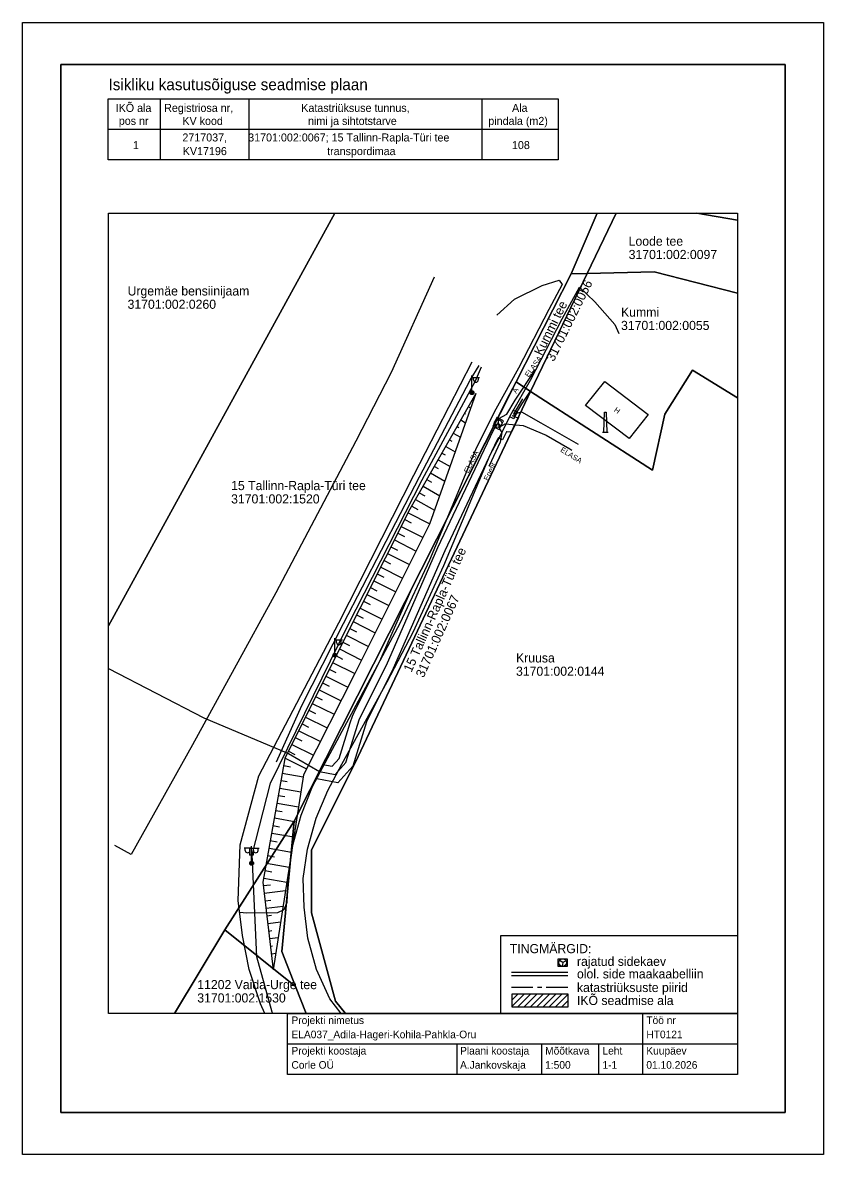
# Model space of a CAD drawing. Extents: x 544680 to 544785, y 6560513 to 6560661.
import ezdxf

# ---------------------------------------------------------------- set-up
doc = ezdxf.new("R2010")
doc.units = 0
for name, color, linetype in [('AED', 7, 'Continuous'), ('HOONE', 7, 'Continuous'), ('KASUTUSALA', 7, 'Continuous'), ('LIIKLUS', 7, 'Continuous'), ('PIIR', 7, 'Continuous'), ('POST', 7, 'Continuous'), ('PR_SIDE', 7, 'Continuous'), ('RAJATIS', 7, 'Continuous'), ('RELJEEF', 7, 'Continuous'), ('SITRASS', 7, 'Continuous'), ('TEE', 7, 'Continuous'), ('VORMISTUS', 7, 'Continuous')]:
    doc.layers.add(name, color=color, linetype=linetype)

msp = doc.modelspace()

# ---------------------------------------------------------------- linework, layer by layer
at = {"layer": 'AED'}
msp.add_lwpolyline([(544713.28, 6560564.18), (544716.58, 6560571.59), (544722.06, 6560582.33), (544722.06, 6560582.33), (544732.03, 6560601.58), (544732.03, 6560601.58), (544738.66, 6560614.26), (544739.83, 6560616.2)], dxfattribs=at)
at = {"layer": 'HOONE'}
msp.add_lwpolyline([(544762.01, 6560609.75), (544759.49, 6560606.62), (544753.8, 6560610.95), (544756.32, 6560614.08), (544762.01, 6560609.75)], dxfattribs=at)
at = {"layer": 'KASUTUSALA'}
msp.add_lwpolyline([(544720.57, 6560563.6), (544721.48, 6560564.61), (544722.94, 6560569.31), (544723.22, 6560570.2), (544723.64, 6560571.04), (544726.77, 6560577.29), (544731.03, 6560587.02), (544743.83, 6560612.38), (544744.68, 6560614.07), (544746.52, 6560612.82), (544745.39, 6560611.12), (544744.4, 6560609.44), (544744.98, 6560609.39), (544744.07, 6560607.46), (544743.45, 6560607.51), (544743.42, 6560607.5), (544742.91, 6560606.44), (544742.35, 6560606.71), (544742.21, 6560606.43), (544735.34, 6560591.89), (544728.58, 6560576.44), (544725.08, 6560569.45), (544723.26, 6560563.6), (544721.3, 6560561.42), (544718.56, 6560561.96), (544718.42, 6560562.04), (544719.33, 6560563.85)], close=True, dxfattribs=at)
at = {"layer": 'LIIKLUS'}
for p, q in [((544709.71, 6560552.8), (544709.71, 6560551.95)), ((544710.21, 6560552.8), (544709.71, 6560552.8)), ((544710.21, 6560551.95), (544709.71, 6560551.95)), ((544709.96, 6560551.95), (544709.96, 6560551.05)), ((544710.21, 6560552.8), (544710.21, 6560551.95)), ((544710.21, 6560551.05), (544709.96, 6560551.05))]:
    msp.add_line(p, q, dxfattribs=at)
at = {"layer": 'PIIR'}
for p, q in [((544691.22, 6560582.03), (544720.91, 6560636.18)), ((544720.91, 6560636.18), (544691.22, 6560582.03)), ((544768.39, 6560636.18), (544773.72, 6560635.28)), ((544773.72, 6560635.28), (544768.39, 6560636.18))]:
    msp.add_line(p, q, dxfattribs=at)
for points in [[(544699.87, 6560531.18), (544706.47, 6560542.13), (544715.57, 6560556.4), (544744.68, 6560614.07), (544751.91, 6560628.23), (544755.32, 6560636.18)], [(544755.32, 6560636.18), (544751.91, 6560628.23), (544754.02, 6560628.26), (544757.82, 6560636.18)], [(544757.82, 6560636.18), (544754.02, 6560628.26), (544762.78, 6560628.47), (544773.72, 6560625.67)], [(544773.72, 6560625.67), (544762.78, 6560628.47), (544754.02, 6560628.26), (544746.58, 6560612.78), (544762.55, 6560602.44), (544764.17, 6560609.79), (544767.79, 6560615.57), (544773.72, 6560611.93)], [(544773.72, 6560611.93), (544767.79, 6560615.57), (544764.17, 6560609.79), (544762.55, 6560602.44), (544746.58, 6560612.78), (544723.97, 6560564.88), (544717.87, 6560552.58), (544717.86, 6560544.37), (544720.99, 6560532.77), (544722.29, 6560531.18)], [(544722.29, 6560531.18), (544720.99, 6560532.77), (544717.86, 6560544.37), (544717.87, 6560552.58), (544723.97, 6560564.88), (544746.58, 6560612.78), (544744.68, 6560614.07), (544715.57, 6560556.4), (544713.97, 6560539.29), (544715.73, 6560534.7), (544717.15, 6560531.18)], [(544717.15, 6560531.18), (544715.73, 6560534.7), (544706.47, 6560542.13), (544699.87, 6560531.18)]]:
    msp.add_lwpolyline(points, dxfattribs=at)
for points in [[(544751.91, 6560628.23), (544744.68, 6560614.07), (544746.58, 6560612.78), (544754.02, 6560628.26)], [(544715.73, 6560534.7), (544713.97, 6560539.29), (544715.57, 6560556.4), (544706.47, 6560542.13)]]:
    msp.add_lwpolyline(points, close=True, dxfattribs=at)
at = {"layer": 'POST'}
for p, q in [((544738.89, 6560612.88), (544738.89, 6560614.88)), ((544738.89, 6560612.88), (544738.89, 6560614.88)), ((544738.89, 6560614.63), (544739.89, 6560614.63)), ((544738.89, 6560614.63), (544739.89, 6560614.63)), ((544739.11, 6560614.31), (544739.11, 6560614.63)), ((544739.11, 6560614.31), (544739.11, 6560614.63)), ((544739.73, 6560614.31), (544739.73, 6560614.63)), ((544739.73, 6560614.31), (544739.73, 6560614.63)), ((544738.89, 6560612.63), (544738.89, 6560612.63)), ((544738.89, 6560612.63), (544738.89, 6560612.63)), ((544720.91, 6560578.43), (544720.91, 6560580.43)), ((544720.91, 6560580.18), (544721.91, 6560580.18)), ((544721.14, 6560579.86), (544721.14, 6560580.18)), ((544721.75, 6560579.86), (544721.75, 6560580.18)), ((544720.91, 6560578.18), (544720.91, 6560578.18)), ((544710, 6560552.88), (544709, 6560552.88)), ((544709.16, 6560552.56), (544709.16, 6560552.88)), ((544709.77, 6560552.56), (544709.77, 6560552.88)), ((544710, 6560551.13), (544710, 6560553.13)), ((544710, 6560552.88), (544711, 6560552.88)), ((544710.23, 6560552.56), (544710.23, 6560552.88)), ((544710.84, 6560552.56), (544710.84, 6560552.88)), ((544710, 6560550.88), (544710, 6560550.88))]:
    msp.add_line(p, q, dxfattribs=at)
msp.add_lwpolyline([(544743.86, 6560609.45), (544744.29, 6560610.35), (544744.83, 6560610.1), (544744.4, 6560609.19)], close=True, dxfattribs=at)
for centre, radius in [((544738.89, 6560612.63), 0.25), ((544738.89, 6560612.63), 0.25), ((544738.89, 6560612.63), 0.225), ((544738.89, 6560612.63), 0.225), ((544738.89, 6560612.63), 0.2), ((544738.89, 6560612.63), 0.2), ((544738.89, 6560612.63), 0.175), ((544738.89, 6560612.63), 0.175), ((544738.89, 6560612.63), 0.15), ((544738.89, 6560612.63), 0.15), ((544738.89, 6560612.63), 0.125), ((544738.89, 6560612.63), 0.125), ((544738.89, 6560612.63), 0.1), ((544738.89, 6560612.63), 0.1), ((544738.89, 6560612.63), 0.075), ((544738.89, 6560612.63), 0.075), ((544738.89, 6560612.63), 0.05), ((544738.89, 6560612.63), 0.05), ((544738.89, 6560612.63), 0.025), ((544738.89, 6560612.63), 0.025), ((544744.43, 6560609.95), 0.0304), ((544744.43, 6560609.95), 0.029), ((544744.43, 6560609.95), 0.0277), ((544744.43, 6560609.95), 0.0263), ((544744.43, 6560609.95), 0.0249), ((544744.43, 6560609.95), 0.0236), ((544744.43, 6560609.95), 0.0222), ((544744.43, 6560609.95), 0.0209), ((544744.43, 6560609.95), 0.0195), ((544744.43, 6560609.95), 0.0181), ((544744.43, 6560609.95), 0.0168), ((544744.43, 6560609.95), 0.0154), ((544744.43, 6560609.95), 0.014), ((544744.43, 6560609.95), 0.0127), ((544744.43, 6560609.95), 0.0113), ((544744.43, 6560609.95), 0.00996), ((544744.43, 6560609.95), 0.0086), ((544744.43, 6560609.95), 0.00724), ((544744.43, 6560609.95), 0.00587), ((544744.43, 6560609.95), 0.00451), ((544744.43, 6560609.95), 0.00315), ((544744.43, 6560609.95), 0.00179), ((544744.43, 6560609.95), 0.000426), ((544744.26, 6560609.59), 0.0304), ((544744.26, 6560609.59), 0.029), ((544744.26, 6560609.59), 0.0277), ((544744.26, 6560609.59), 0.0263), ((544744.26, 6560609.59), 0.0249), ((544744.26, 6560609.59), 0.0236), ((544744.26, 6560609.59), 0.0222), ((544744.26, 6560609.59), 0.0209), ((544744.26, 6560609.59), 0.0195), ((544744.26, 6560609.59), 0.0181), ((544744.26, 6560609.59), 0.0168), ((544744.26, 6560609.59), 0.0154), ((544744.26, 6560609.59), 0.014), ((544744.26, 6560609.59), 0.0127), ((544744.26, 6560609.59), 0.0113), ((544744.26, 6560609.59), 0.00996), ((544744.26, 6560609.59), 0.0086), ((544744.26, 6560609.59), 0.00724), ((544744.26, 6560609.59), 0.00587), ((544744.26, 6560609.59), 0.00451), ((544744.26, 6560609.59), 0.00315), ((544744.26, 6560609.59), 0.00179), ((544744.26, 6560609.59), 0.000426), ((544720.91, 6560578.18), 0.25), ((544720.91, 6560578.18), 0.225), ((544720.91, 6560578.18), 0.2), ((544720.91, 6560578.18), 0.175), ((544720.91, 6560578.18), 0.15), ((544720.91, 6560578.18), 0.125), ((544720.91, 6560578.18), 0.1), ((544720.91, 6560578.18), 0.075), ((544720.91, 6560578.18), 0.05), ((544720.91, 6560578.18), 0.025), ((544710, 6560550.88), 0.25), ((544710, 6560550.88), 0.225), ((544710, 6560550.88), 0.2), ((544710, 6560550.88), 0.175), ((544710, 6560550.88), 0.15), ((544710, 6560550.88), 0.125), ((544710, 6560550.88), 0.1), ((544710, 6560550.88), 0.075), ((544710, 6560550.88), 0.05), ((544710, 6560550.88), 0.025)]:
    msp.add_circle(centre, radius, dxfattribs=at)
for centre in [(544739.42, 6560614.31), (544739.42, 6560614.31), (544721.44, 6560579.86), (544709.47, 6560552.56), (544710.53, 6560552.56)]:
    msp.add_arc(centre, 0.306, 180, 0, dxfattribs=at)
at = {"layer": 'PR_SIDE'}
for p, q in [((544742.31, 6560608.57), (544741.89, 6560608.29)), ((544742.31, 6560609.07), (544742.31, 6560608.57)), ((544742.31, 6560608.57), (544742.72, 6560608.29))]:
    msp.add_line(p, q, dxfattribs=at)
for points in [[(544742.31, 6560608.57), (544742.43, 6560609.23), (544743.46, 6560609.82), (544744.55, 6560611.66), (544747.24, 6560615.69)], [(544724.15, 6560569.83), (544727.67, 6560576.87), (544734.43, 6560592.31), (544741.31, 6560606.87), (544741.9, 6560608.04), (544742.31, 6560608.57)], [(544742.31, 6560608.57), (544742.65, 6560608.21), (544743.23, 6560608.54), (544745.59, 6560608.34), (544748.64, 6560607.07), (544751.72, 6560605.28), (544751.99, 6560605.1)], [(544691.22, 6560576.42), (544703.74, 6560569.97), (544714.85, 6560565.28), (544718.92, 6560562.91), (544720.94, 6560562.51), (544722.37, 6560564.11), (544724.15, 6560569.83)]]:
    msp.add_lwpolyline(points, dxfattribs=at)
msp.add_lwpolyline([(544742.17, 6560609.35), (544741.61, 6560608.18), (544742.44, 6560607.78), (544743.01, 6560608.95)], close=True, dxfattribs=at)
msp.add_circle((544742.31, 6560608.57), 0.5, dxfattribs=at)
at = {"layer": 'RAJATIS'}
for p, q in [((544756.29, 6560610.08), (544756.48, 6560610.08)), ((544756.48, 6560610.08), (544756.58, 6560607.39)), ((544756.77, 6560607.39), (544756, 6560607.39)), ((544756.58, 6560607.39), (544756.19, 6560607.39))]:
    msp.add_line(p, q, dxfattribs=at)
msp.add_lwpolyline([(544756.48, 6560610.08), (544756.58, 6560607.39), (544756.19, 6560607.39), (544756.29, 6560610.08)], close=True, dxfattribs=at)
at = {"layer": 'RELJEEF'}
for p, q in [((544738.91, 6560611.65), (544738.96, 6560611.63)), ((544739.41, 6560612.52), (544739.41, 6560612.52)), ((544737.92, 6560609.92), (544738.06, 6560609.84)), ((544738.42, 6560610.79), (544738.73, 6560610.61)), ((544737.43, 6560609.05), (544738.05, 6560608.69)), ((544736.44, 6560607.31), (544737.38, 6560606.78)), ((544736.93, 6560608.18), (544737.17, 6560608.04)), ((544735.45, 6560605.57), (544736.7, 6560604.86)), ((544735.94, 6560606.44), (544736.27, 6560606.25)), ((544734.46, 6560603.83), (544736.02, 6560602.94)), ((544734.95, 6560604.7), (544735.38, 6560604.46)), ((544733.96, 6560602.96), (544734.48, 6560602.67)), ((544732.97, 6560601.23), (544733.58, 6560600.88)), ((544733.47, 6560602.1), (544735.34, 6560601.03)), ((544731.98, 6560599.49), (544732.69, 6560599.09)), ((544732.48, 6560600.36), (544734.67, 6560599.11)), ((544731.49, 6560598.62), (544733.99, 6560597.2)), ((544730.52, 6560596.87), (544733.37, 6560595.43)), ((544730.99, 6560597.75), (544731.79, 6560597.3)), ((544729.62, 6560595.08), (544732.48, 6560593.64)), ((544730.07, 6560595.98), (544730.93, 6560595.54)), ((544729.17, 6560594.19), (544730.03, 6560593.76)), ((544728.27, 6560592.41), (544729.13, 6560591.97)), ((544728.72, 6560593.3), (544731.58, 6560591.85)), ((544727.37, 6560590.62), (544728.23, 6560590.19)), ((544727.82, 6560591.51), (544730.69, 6560590.07)), ((544726.92, 6560589.73), (544729.79, 6560588.28)), ((544726.02, 6560587.94), (544728.89, 6560586.49)), ((544726.47, 6560588.84), (544727.33, 6560588.4)), ((544725.12, 6560586.16), (544728, 6560584.7)), ((544725.57, 6560587.05), (544726.43, 6560586.61)), ((544724.67, 6560585.26), (544725.53, 6560584.83)), ((544723.76, 6560583.48), (544724.63, 6560583.04)), ((544724.21, 6560584.37), (544727.1, 6560582.91)), ((544722.86, 6560581.69), (544723.73, 6560581.25)), ((544723.31, 6560582.59), (544726.21, 6560581.13)), ((544722.41, 6560580.8), (544725.31, 6560579.34)), ((544721.51, 6560579.02), (544724.41, 6560577.55)), ((544721.96, 6560579.91), (544722.83, 6560579.47)), ((544720.61, 6560577.23), (544723.53, 6560575.78)), ((544721.06, 6560578.12), (544721.93, 6560577.68)), ((544720.17, 6560576.33), (544721.04, 6560575.9)), ((544719.28, 6560574.54), (544720.15, 6560574.11)), ((544719.73, 6560575.44), (544722.62, 6560574)), ((544718.39, 6560572.75), (544719.26, 6560572.32)), ((544718.84, 6560573.64), (544721.72, 6560572.21)), ((544717.95, 6560571.85), (544720.82, 6560570.43)), ((544717.06, 6560570.06), (544719.92, 6560568.64)), ((544717.5, 6560570.96), (544718.36, 6560570.53)), ((544716.17, 6560568.27), (544719.02, 6560566.86)), ((544716.61, 6560569.17), (544717.47, 6560568.74)), ((544715.72, 6560567.37), (544716.58, 6560566.95)), ((544714.83, 6560565.58), (544715.68, 6560565.16)), ((544715.28, 6560566.48), (544718.12, 6560565.07)), ((544714.2, 6560563.71), (544715.09, 6560563.55)), ((544714.39, 6560564.69), (544717.21, 6560563.29)), ((544714.02, 6560562.72), (544716.77, 6560562.24)), ((544713.68, 6560560.75), (544716.46, 6560560.26)), ((544713.85, 6560561.74), (544714.68, 6560561.59)), ((544713.5, 6560559.77), (544714.34, 6560559.62)), ((544713.15, 6560557.8), (544714.01, 6560557.65)), ((544713.33, 6560558.78), (544716.16, 6560558.28)), ((544712.98, 6560556.82), (544715.85, 6560556.31)), ((544712.63, 6560554.85), (544715.54, 6560554.33)), ((544712.8, 6560555.83), (544713.67, 6560555.68)), ((544712.45, 6560553.86), (544713.34, 6560553.71)), ((544712.11, 6560551.89), (544713, 6560551.73)), ((544712.28, 6560552.88), (544715.24, 6560552.35)), ((544711.93, 6560550.91), (544714.93, 6560550.38)), ((544711.58, 6560548.94), (544714.62, 6560548.4)), ((544711.76, 6560549.92), (544712.66, 6560549.76)), ((544711.53, 6560547.95), (544712.46, 6560548.06)), ((544711.65, 6560546.96), (544714.45, 6560547.29)), ((544711.77, 6560545.96), (544712.52, 6560546.05)), ((544711.89, 6560544.97), (544714.13, 6560545.23)), ((544712, 6560543.98), (544712.59, 6560544.05)), ((544712.12, 6560542.98), (544713.81, 6560543.18)), ((544712.24, 6560541.99), (544712.66, 6560542.04)), ((544712.35, 6560541), (544713.49, 6560541.13)), ((544712.47, 6560540), (544712.73, 6560540.03)), ((544712.59, 6560539.01), (544713.17, 6560539.08)), ((544712.7, 6560538.02), (544712.8, 6560538.03)), ((544712.82, 6560537.02), (544712.85, 6560537.03))]:
    msp.add_line(p, q, dxfattribs=at)
for points in [[(544739.41, 6560612.52), (544730.76, 6560597.35), (544720.98, 6560577.97), (544714.36, 6560564.63), (544711.48, 6560548.38), (544712.83, 6560536.91)], [(544739.41, 6560612.52), (544733.34, 6560595.36), (544723.57, 6560575.88), (544716.81, 6560562.49), (544712.83, 6560536.91)]]:
    msp.add_lwpolyline(points, dxfattribs=at)
at = {"layer": 'SITRASS'}
for points in [[(544745.52, 6560611.83), (544744.36, 6560609.8)], [(544744.36, 6560609.8), (544745.39, 6560610.11)], [(544745.39, 6560610.11), (544747.93, 6560608.66), (544752.83, 6560605.88)], [(544742.33, 6560608.58), (544742.5, 6560607.89), (544742.79, 6560607.42), (544742.59, 6560606.14), (544741.14, 6560603.05), (544741.12, 6560602.98)]]:
    msp.add_lwpolyline(points, dxfattribs=at)
at = {"layer": 'TEE'}
for points in [[(544733.93, 6560627.79), (544728.29, 6560615.27), (544723.65, 6560606.27), (544713.17, 6560586.38), (544702.25, 6560566.4), (544694.21, 6560552.03), (544692.04, 6560553.19)], [(544742.17, 6560622.8), (544744.48, 6560624.88), (544748.08, 6560626.69), (544750.32, 6560627.37), (544750.73, 6560626.82), (544748.99, 6560623.52), (544744.98, 6560615.83), (544742.01, 6560610.45), (544739.45, 6560605.33)], [(544741.3, 6560604.46), (544742.19, 6560606.19), (544744.09, 6560609.88), (544746.56, 6560614.28), (544750.73, 6560622.32), (544752.99, 6560626.47), (544755.01, 6560624.54), (544757.63, 6560621.57), (544758.14, 6560620.4)], [(544711.73, 6560531.18), (544711.14, 6560532.42), (544709.66, 6560536.96), (544708.78, 6560541.41), (544708.25, 6560546.01), (544708.51, 6560553.28), (544710.95, 6560562.37), (544721.45, 6560582.41), (544731.29, 6560601.79), (544738.93, 6560616.66)], [(544712.79, 6560531.18), (544712.7, 6560531.35), (544710.7, 6560538.6), (544710.05, 6560551.98), (544712.49, 6560561.4), (544722.62, 6560582.08), (544732.35, 6560601.2), (544739.36, 6560614.18), (544740.16, 6560616.04)], [(544739.45, 6560605.33), (544737.02, 6560599.51), (544733.31, 6560590.65), (544729.42, 6560582.36), (544725.87, 6560575.64), (544719.95, 6560564.66), (544717.92, 6560560.92), (544716.44, 6560557.13), (544715.36, 6560553.23), (544714.75, 6560548.81), (544714.61, 6560545.73), (544714.24, 6560544.77), (544713.4, 6560544.38), (544709.38, 6560544.33), (544708.39, 6560544.4)], [(544721.75, 6560531.18), (544720.27, 6560533.09), (544718.52, 6560536.96), (544717.37, 6560541.04), (544716.89, 6560545.1), (544716.75, 6560548.88), (544717.31, 6560552.71), (544718.47, 6560556.79), (544720, 6560560.44), (544721.83, 6560563.88), (544727.78, 6560574.7), (544731.18, 6560581.22), (544735.21, 6560589.95), (544738.88, 6560598.74), (544741.3, 6560604.46)]]:
    msp.add_lwpolyline(points, dxfattribs=at)
at = {"layer": 'VORMISTUS'}
for p, q in [((544697.99, 6560651.19), (544697.99, 6560643.19)), ((544709.64, 6560651.19), (544709.64, 6560643.19)), ((544740.19, 6560651.19), (544740.19, 6560643.19)), ((544691.19, 6560647.19), (544750.19, 6560647.19)), ((544750.79, 6560537.85), (544750.36, 6560538.1)), ((544750.79, 6560537.85), (544750.72, 6560537.35)), ((544751.24, 6560538.06), (544750.79, 6560537.85)), ((544744.07, 6560536.59), (544751.46, 6560536.59)), ((544744.07, 6560536.15), (544751.46, 6560536.15)), ((544746.89, 6560534.58), (544744.07, 6560534.58)), ((544748.06, 6560534.58), (544747.47, 6560534.58)), ((544751.46, 6560534.58), (544748.64, 6560534.58)), ((544745.8, 6560533.76), (544744.18, 6560532.14)), ((544744.97, 6560533.76), (544744.18, 6560532.96)), ((544746.62, 6560533.76), (544744.88, 6560532.01)), ((544747.45, 6560533.76), (544745.7, 6560532.01)), ((544748.27, 6560533.76), (544746.52, 6560532.01)), ((544749.09, 6560533.76), (544747.35, 6560532.01)), ((544749.92, 6560533.76), (544748.17, 6560532.01)), ((544750.74, 6560533.76), (544748.99, 6560532.01)), ((544751.46, 6560533.65), (544749.82, 6560532.01)), ((544751.46, 6560532.83), (544750.64, 6560532.01)), ((544761.27, 6560531.18), (544761.27, 6560527.18)), ((544714.72, 6560527.18), (544773.72, 6560527.18)), ((544736.91, 6560527.18), (544736.91, 6560523.18)), ((544747.99, 6560527.18), (544747.99, 6560523.18)), ((544755.5, 6560527.18), (544755.5, 6560523.18)), ((544761.27, 6560527.18), (544761.27, 6560523.18))]:
    msp.add_line(p, q, dxfattribs=at)
for points in [[(544679.97, 6560661.18), (544784.97, 6560661.18), (544784.97, 6560512.68), (544679.97, 6560512.68)], [(544684.97, 6560518.18), (544779.97, 6560518.18), (544779.97, 6560655.68), (544684.97, 6560655.68)], [(544684.97, 6560655.68), (544779.97, 6560655.68), (544779.97, 6560518.18), (544684.97, 6560518.18)], [(544691.19, 6560651.19), (544750.19, 6560651.19), (544750.19, 6560643.19), (544691.19, 6560643.19)], [(544773.72, 6560531.18), (544691.22, 6560531.18), (544691.22, 6560636.18), (544773.72, 6560636.18)], [(544742.66, 6560531.18), (544742.66, 6560541.38), (544773.72, 6560541.38), (544773.72, 6560531.18)], [(544751.44, 6560538.31), (544750.14, 6560538.31), (544750.14, 6560537.38), (544751.44, 6560537.38)], [(544744.18, 6560533.76), (544751.46, 6560533.76), (544751.46, 6560532.01), (544744.18, 6560532.01)], [(544714.72, 6560531.18), (544773.72, 6560531.18), (544773.72, 6560523.18), (544714.72, 6560523.18)]]:
    msp.add_lwpolyline(points, close=True, dxfattribs=at)
msp.add_circle((544750.79, 6560537.85), 0.5, dxfattribs=at)

# ---------------------------------------------------------------- texts
at = {"layer": 'HOONE'}
msp.add_text('H', height=0.7, rotation=324.3652, dxfattribs=at).set_placement((544757.44, 6560610.21))
at = {"layer": 'PIIR'}
for s, p in [('Loode tee', (544759.44, 6560631.91)), ('31701:002:0097', (544759.44, 6560630.16)), ('Urgemäe bensiinijaam', (544693.73, 6560625.38)), ('31701:002:0260', (544693.73, 6560623.63)), ('Kummi', (544758.44, 6560622.6)), ('31701:002:0055', (544758.44, 6560620.85)), ('15 Tallinn-Rapla-Türi tee', (544707.31, 6560599.84)), ('31701:002:1520', (544707.31, 6560598.09)), ('Kruusa', (544744.67, 6560577.23)), ('31701:002:0144', (544744.67, 6560575.48)), ('11202 Vaida-Urge tee', (544702.87, 6560534.36)), ('31701:002:1530', (544702.87, 6560532.61))]:
    msp.add_text(s, height=1.2, dxfattribs=at).set_placement(p)
for s, rotation, p in [('31701:002:0056', 63.8047, (544749.62, 6560616.63)), ('Kummi tee', 63.8047, (544748.05, 6560617.41)), ('15 Tallinn-Rapla-Türi tee', 65.8525, (544730.95, 6560575.86)), ('31701:002:0067', 65.8525, (544732.55, 6560575.14))]:
    msp.add_text(s, height=1.2, rotation=rotation, dxfattribs=at).set_placement(p)
at = {"layer": 'SITRASS'}
for s, rotation, p in [('ELASA', 53.9764, (544746.32, 6560614.59)), ('ELASA', 328.2415, (544750.41, 6560604.95)), ('ELASA', 64.2323, (544738.43, 6560602.01)), ('Enefit', 64.2323, (544741.02, 6560601))]:
    msp.add_text(s, height=0.7, rotation=rotation, dxfattribs=at).set_placement(p)
at = {"layer": 'TEE'}
msp.add_text('A', height=0.7, rotation=59.2055, dxfattribs=at).set_placement((544744.71, 6560612.47))
at = {"layer": 'VORMISTUS'}
for s, height, p in [('Isikliku kasutusõiguse seadmise plaan', 1.5, (544691.23, 6560652.32)), ('IKÕ ala', 1.05, (544692.17, 6560649.47)), ('Registriosa nr,', 1.05, (544698.53, 6560649.47)), ('Katastriüksuse tunnus,', 1.05, (544716.51, 6560649.47)), ('Ala', 1.05, (544744.15, 6560649.47)), ('pos nr', 1.05, (544692.58, 6560647.77)), ('KV kood', 1.05, (544700.92, 6560647.76)), ('nimi ja sihtotstarve', 1.05, (544717.4, 6560647.76)), ('pindala (m2)', 1.05, (544741.04, 6560647.76)), ('1', 1.05, (544694.44, 6560644.59)), ('2717037,', 1.05, (544700.92, 6560645.59)), ('31701:002:0067; 15 Tallinn-Rapla-Türi tee', 1.05, (544709.55, 6560645.59)), ('108', 1.05, (544744.14, 6560644.59)), ('KV17196', 1.05, (544700.97, 6560643.8)), ('transpordimaa', 1.05, (544719.9, 6560643.8)), ('TINGMÄRGID:', 1.2, (544743.86, 6560539.08)), ('rajatud sidekaev', 1.2, (544752.66, 6560537.41)), ('olol. side maakaabelliin', 1.2, (544752.66, 6560535.77)), ('katastriüksuste piirid', 1.2, (544752.66, 6560533.98)), ('IKÕ seadmise ala', 1.2, (544752.66, 6560532.28)), ('Projekti nimetus', 1, (544715.22, 6560529.78)), ('Töö nr', 1, (544761.76, 6560529.78)), ('ELA037_Adila-Hageri-Kohila-Pahkla-Oru', 1, (544715.22, 6560527.92)), ('HT0121', 1, (544761.76, 6560527.92)), ('Projekti koostaja', 1, (544715.22, 6560525.78)), ('Plaani koostaja', 1, (544737.33, 6560525.78)), ('Mõõtkava', 1, (544748.49, 6560525.78)), ('Leht', 1, (544756, 6560525.78)), ('Kuupäev', 1, (544761.76, 6560525.78)), ('Corle OÜ', 1, (544715.22, 6560523.92)), ('A.Jankovskaja', 1, (544737.33, 6560523.92)), ('1:500', 1, (544748.49, 6560523.92)), ('1-1', 1, (544756, 6560523.92)), ('01.10.2026', 1, (544761.76, 6560523.92))]:
    msp.add_text(s, height=height, dxfattribs=at).set_placement(p)

doc.saveas('drawing.dxf')
